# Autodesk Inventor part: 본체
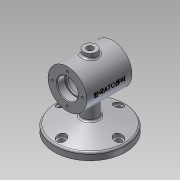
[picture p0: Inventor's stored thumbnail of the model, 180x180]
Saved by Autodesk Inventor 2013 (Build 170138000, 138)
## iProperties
Created: 2018-12
Part Number: 본체
Material: 알루미늄 6061
Document SubType Name: Modeling
Designer: Administrator
Density: 2.71 g/cm^3
Mass: 687.672 g
Surface Area: 555.63 cm^2
Volume: 253.753 cm^3
Author: Administrator
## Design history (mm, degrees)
sketch "스케치1"
  geometry: L1 (-35, 0)-(35, 0); L2 (-35, 16)-(-35, 30); L3 (-35, 30)-(35, 30); L4 (35, 30)-(35, 16); L5 (-35, 16)-(-23, 16); L6 (-23, 16)-(-23, 14); L7 (-23, 14)-(-20, 14); L8 (-20, 14)-(-20, 25); L9 (-20, 25)-(20, 25); L10 (20, 25)-(20, 14); L11 (20, 14)-(23, 14); L12 (23, 14)-(23, 16); L13 (23, 16)-(35, 16); 1 further point
  constraints: 26 end point, 6 parallel, 5 perpendicular, 2 collinear, 2 point on line, 1 horizontal, 1 midpoint, 1 vertical
  dimensions: "d0" = 70 distance of L1.start L1.end; "d2" = 35 distance of point (0, 0) L1.start; "d3" = 60 diameter of L3 L1; "d5" = 32 diameter of L5 L1; "d6" = 50 diameter of L9 L1; "d7" = 28 diameter of L7 L1; "d8" = 12 distance between parallel lines of L2 L6; "d9" = 3 distance between parallel lines of L8 L6; "d10" = 3 distance between parallel lines of L12 L10; "d11" = 12 distance between parallel lines of L4 L12
revolve "회전1" sketch "스케치1" stored, may be unused: angle "d12" = 90 deg
node "작업 평면1"
sketch "스케치2"
  geometry: L1 (35, 30)-(35, -30) reference; C1 r 10 at (0, 0); 1 further point
  constraints: 1 centre point, 1 coincident
  dimensions: "d14" = 35 distance from line of L1 C1.centre; "d15" = 20 diameter of C1
extrude "돌출1" join sketch "스케치2" stored distance "d16" = 10; taper "d17" = 0 deg
hole "구멍1" diameter "d20" = 10; stored, may be unused: countersink angle "d24" = 90 deg, drill point angle "d26" = 0 deg; dims "d18" = 10, "d19" = 10, "d21" = 6, "d22" = 4, "d23" = 2, "d25" = 8
sketch "스케치3"
  geometry: L1 (-75, 55)-(-64, 55); L2 (-64, 55)-(-52.478, 12); L3 (-30, 0)-(-75, 0); L4 (-75, 55)-(-75, 0); L5 (37, 10)-(37, -10) reference; L6 (-52.478, 12)-(-27.495, 12); A1 r 30 centre (0, 0) between (-30, 0) and (-27.495, 12) reference; A2 r 25 centre (0, 0) between (-21.932, 12) and (-25, 0) reference; 1 further point
  constraints: 10 end point, 4 point on circle, 2 perpendicular, 1 point on line
  dimensions: "d29" = 110 diameter of L1 L3; "d31" = 75 deg angle of L2 L1; "d33" = 75 distance from line of L4 point (0, 0); "d34" = 11 distance of L1.start L1.end; "d35" = 112 distance between parallel lines of L4 L5 (derived); "d37" = 24 diameter of L6 L3
revolve "회전2" sketch "스케치3" stored, may be unused: angle "d36" = 90 deg
sketch "스케치5"
  geometry: C1 r 16 at (0, 0) reference; 1 further point
  constraints: 1 vertical alignment
  dimensions: "d38" = 23 distance of C1.centre point (0, 23)
hole "구멍2" sketch "스케치5" at (0, 23) diameter "d39" = 3.242; stored, may be unused: countersink angle "d43" = 90 deg, drill point angle "d45" = 118 deg; dims "d40" = 8, "d41" = 4, "d42" = 2, "d44" = 10
sketch "스케치6"
  geometry: C1 r 55 at (0, 0) reference; C2 r 4.5 at (44, 0)
  constraints: 1 centre point, 1 horizontal alignment
  dimensions: "d49" = 44 distance of C1.centre C2.centre; "d50" = 9 diameter of C2
extrude "돌출2" cut sketch "스케치6" distance "d51" = 10; taper "d52" = 0 deg
hole "구멍3" diameter "d55" = 14; stored, may be unused: countersink angle "d59" = 90 deg, drill point angle "d61" = 0 deg; dims "d53" = 10, "d54" = 10, "d56" = 8, "d57" = 4, "d58" = 2, "d60" = 10
fillet "모깎기1" dims "d65" = 3
fillet "모깎기2" dims "d66" = 0.3
fillet "모깎기3" dims "d67" = 3
chamfer "모따기1" distance "d68" = 1; stored, may be unused: second distance "d69" = 2, angle "d70" = 45 deg
sketch "스케치7"
  geometry: L1 (0, 0)-(0, 30); 1 further point
  constraints: 2 end point, 1 vertical, 1 vertical alignment, 1 other
node "작업 평면2"
sketch "스케치8"
  geometry: L1 (-35, -30)-(-35, 30) reference; L2 (-35, 30)-(35, 30) reference; 2 further points
  constraints: 1 other
  dimensions: "d71" = 35 distance from line of point (0, 0) L1; "d72" = 30 distance from line of point (0, 0) L2
feature "엠보싱1" sketch "스케치8" dims "d0" = 70, "d2" = 35, "d3" = 60, "d5" = 32, "d6" = 50, "d7" = 28, "d8" = 12, "d9" = 3, "d10" = 3, "d11" = 12, "d73" = 0.5, "d74" = 0
node "솔리드1"
pattern_circular "원형 패턴1" dims angle "d47" = 360 deg
mirror "대칭1"
pattern_circular "원형 패턴2" dims angle "d63" = 360 deg
other parameters: "d13" = 37
